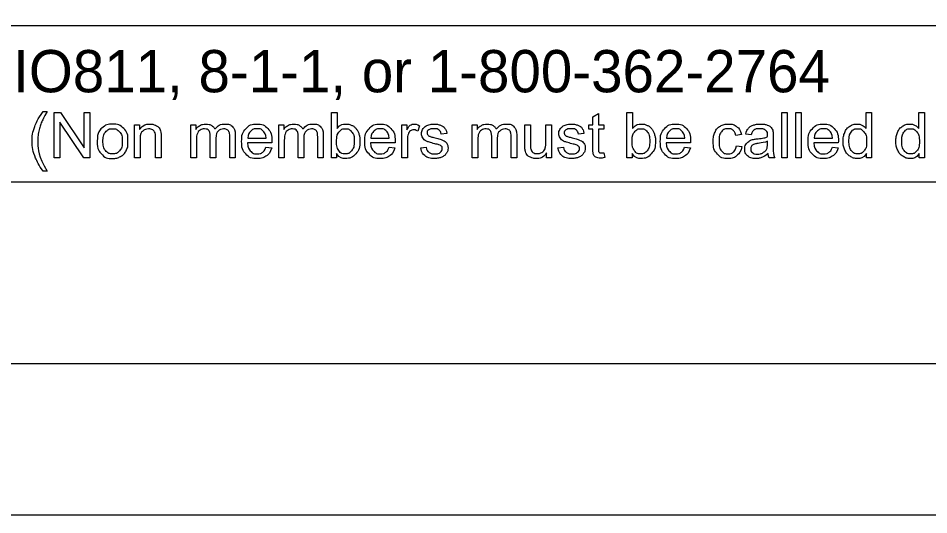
# Model space of a CAD drawing. Extents: x -20.5 to 34, y -66 to 23.9.
# Drawn here: x 15.219 to 18.236, y 0 to 1.645 of the extents above; entities that cross this region are included whole.
import ezdxf

# ---------------------------------------------------------------- set-up
doc = ezdxf.new("R2010")
doc.units = 0
for name, color, linetype in [('SH_Border', 7, 'Continuous'), ('SH_Cut_Line', 7, 'Continuous'), ('SH_Data', 7, 'Continuous'), ('SH_Text', 7, 'Continuous')]:
    doc.layers.add(name, color=color, linetype=linetype)

msp = doc.modelspace()

# ---------------------------------------------------------------- linework, layer by layer
at = {"layer": 'SH_Border'}
msp.add_lwpolyline([(1.5, 21.5), (33.5, 21.5), (33.5, 0.5), (1.5, 0.5)], close=True, dxfattribs=at)
at = {"layer": 'SH_Cut_Line'}
msp.add_lwpolyline([(0, 0), (34, 0), (34, 22), (0, 22)], close=True, dxfattribs=at)
at = {"layer": 'SH_Data'}
for p, q in [((19.1267, 1.6197), (14.8767, 1.6197)), ((19.1267, 1.1019), (14.8767, 1.1019))]:
    msp.add_line(p, q, dxfattribs=at)
at = {"layer": 'SH_Text'}
for points in [[(15.3013, 1.3357), (15.3145, 1.3357)], [(15.338, 1.183), (15.338, 1.3332), (15.3584, 1.3332), (15.4374, 1.2152), (15.4374, 1.3332), (15.4564, 1.3332), (15.4564, 1.183), (15.4361, 1.183), (15.357, 1.3009), (15.357, 1.183), (15.338, 1.183)], [(16.2735, 1.183), (16.2565, 1.183), (16.2565, 1.3332), (16.2749, 1.3332), (16.2749, 1.2797)], [(17.1225, 1.2149), (17.1225, 1.2775), (17.1088, 1.2775), (17.1088, 1.2919), (17.1225, 1.2919), (17.1225, 1.3188), (17.1409, 1.3299), (17.1409, 1.2919), (17.1593, 1.2919), (17.1593, 1.2775), (17.1409, 1.2775), (17.1409, 1.2138)], [(17.2526, 1.183), (17.2355, 1.183), (17.2355, 1.3332), (17.254, 1.3332), (17.254, 1.2797)], [(17.7482, 1.183), (17.7482, 1.3332), (17.7667, 1.3332), (17.7667, 1.183), (17.7482, 1.183)], [(17.7948, 1.183), (17.7948, 1.3332), (17.8132, 1.3332), (17.8132, 1.183), (17.7948, 1.183)], [(18.0277, 1.2793), (18.0277, 1.3332), (18.0461, 1.3332), (18.0461, 1.183), (18.0291, 1.183)], [(18.2026, 1.2793), (18.2026, 1.3332), (18.221, 1.3332), (18.221, 1.183), (18.2039, 1.183)], [(15.604, 1.183), (15.604, 1.2919), (15.6206, 1.2919), (15.6206, 1.2764)], [(15.7904, 1.183), (15.7904, 1.2919), (15.8069, 1.2919), (15.8069, 1.2765)], [(16.0818, 1.183), (16.0818, 1.2919), (16.0983, 1.2919), (16.0983, 1.2765)], [(16.4896, 1.183), (16.4896, 1.2919), (16.5062, 1.2919), (16.5062, 1.2754)], [(16.5486, 1.2884), (16.5422, 1.2713)], [(16.7228, 1.183), (16.7228, 1.2919), (16.7393, 1.2919), (16.7393, 1.2765)], [(16.8971, 1.2245), (16.8971, 1.2919), (16.9155, 1.2919), (16.9155, 1.2315)], [(16.9668, 1.2336), (16.9668, 1.2919), (16.9852, 1.2919), (16.9852, 1.183), (16.9688, 1.183)], [(15.6224, 1.2424), (15.6224, 1.183), (15.604, 1.183)], [(15.6924, 1.2499), (15.6924, 1.183), (15.6739, 1.183), (15.6739, 1.2492)], [(15.8089, 1.2394), (15.8089, 1.183), (15.7904, 1.183)], [(15.8735, 1.2462), (15.8735, 1.183), (15.8551, 1.183), (15.8551, 1.2537)], [(15.9379, 1.2577), (15.9379, 1.183), (15.9195, 1.183), (15.9195, 1.2515)], [(15.979, 1.2478), (16.0398, 1.2478)], [(16.1002, 1.2394), (16.1002, 1.183), (16.0818, 1.183)], [(16.1649, 1.2462), (16.1649, 1.183), (16.1465, 1.183), (16.1465, 1.2537)], [(16.2293, 1.2577), (16.2293, 1.183), (16.2109, 1.183), (16.2109, 1.2515)], [(16.387, 1.2478), (16.4478, 1.2478)], [(16.508, 1.24), (16.508, 1.183), (16.4896, 1.183)], [(16.6386, 1.2637), (16.6205, 1.2613)], [(16.7412, 1.2394), (16.7412, 1.183), (16.7228, 1.183)], [(16.8059, 1.2462), (16.8059, 1.183), (16.7875, 1.183), (16.7875, 1.2537)], [(16.8703, 1.2577), (16.8703, 1.183), (16.8519, 1.183), (16.8519, 1.2515)], [(17.0932, 1.2637), (17.0751, 1.2613)], [(17.3661, 1.2478), (17.4269, 1.2478)], [(17.6146, 1.2598), (17.5966, 1.2571)], [(17.6471, 1.2583), (17.629, 1.2607)], [(17.7014, 1.2309), (17.7015, 1.2376)], [(17.7201, 1.2532), (17.7201, 1.2286)], [(17.8557, 1.2478), (17.9165, 1.2478)], [(16.0592, 1.2327), (15.978, 1.2327)], [(16.0396, 1.2181), (16.0587, 1.2157)], [(16.4672, 1.2327), (16.386, 1.2327)], [(16.4476, 1.2181), (16.4666, 1.2157)], [(16.5522, 1.2155), (16.5704, 1.2184)], [(17.0068, 1.2155), (17.0249, 1.2184)], [(17.4462, 1.2327), (17.3651, 1.2327)], [(17.4267, 1.2181), (17.4457, 1.2157)], [(17.5982, 1.2228), (17.6163, 1.2204)], [(17.9358, 1.2327), (17.8547, 1.2327)], [(17.9163, 1.2181), (17.9353, 1.2157)], [(16.2735, 1.1966), (16.2735, 1.183)], [(16.9688, 1.183), (16.9688, 1.1991)], [(17.1593, 1.1994), (17.1619, 1.1832)], [(17.2526, 1.1966), (17.2526, 1.183)], [(17.7259, 1.183), (17.7067, 1.183)], [(18.0291, 1.183), (18.0291, 1.1967)], [(18.2039, 1.183), (18.2039, 1.1967)], [(15.3145, 1.1388), (15.3013, 1.1388)]]:
    msp.add_lwpolyline(points, dxfattribs=at)
for points, degree in [([(15.3013, 1.1388), (15.286, 1.1581), (15.2755, 1.1839), (15.2649, 1.2097), (15.2649, 1.2374), (15.2649, 1.2617), (15.2728, 1.2841), (15.282, 1.31), (15.3013, 1.3357)], 3), ([(15.3145, 1.3357), (15.3021, 1.3144), (15.2981, 1.3053), (15.2919, 1.2911), (15.2883, 1.2758), (15.2839, 1.2566), (15.2839, 1.2373), (15.2839, 1.188), (15.3145, 1.1388)], 3), ([(15.4805, 1.2374), (15.4805, 1.2676), (15.4973, 1.2822), (15.5113, 1.2943), (15.5315, 1.2943), (15.5539, 1.2943), (15.5682, 1.2796), (15.5824, 1.2649), (15.5824, 1.239), (15.5824, 1.218), (15.5761, 1.206), (15.5698, 1.1939), (15.5578, 1.1873), (15.5457, 1.1806), (15.5315, 1.1806), (15.5087, 1.1806), (15.4946, 1.1953), (15.4805, 1.2099), (15.4805, 1.2374)], 3), ([(15.4995, 1.2374), (15.4995, 1.2165), (15.5086, 1.2061), (15.5177, 1.1957), (15.5315, 1.1957), (15.5452, 1.1957), (15.5543, 1.2062), (15.5634, 1.2166), (15.5634, 1.238), (15.5634, 1.2582), (15.5542, 1.2686), (15.5451, 1.279), (15.5315, 1.279), (15.5177, 1.279), (15.5086, 1.2687), (15.4995, 1.2583), (15.4995, 1.2374)], 3), ([(15.6206, 1.2764), (15.6326, 1.2943), (15.6552, 1.2943), (15.665, 1.2943), (15.6733, 1.2907), (15.6815, 1.2872), (15.6856, 1.2815), (15.6897, 1.2757), (15.6913, 1.2678), (15.6924, 1.2627), (15.6924, 1.2499)], 3), ([(15.6739, 1.2492), (15.6739, 1.2604), (15.6718, 1.266), (15.6696, 1.2716), (15.6642, 1.2749), (15.6587, 1.2782), (15.6513, 1.2782), (15.6395, 1.2782), (15.631, 1.2708), (15.6224, 1.2633), (15.6224, 1.2424)], 3), ([(15.8069, 1.2765), (15.812, 1.2845), (15.8205, 1.2894), (15.829, 1.2943), (15.8399, 1.2943), (15.852, 1.2943), (15.8597, 1.2892), (15.8675, 1.2842), (15.8706, 1.2752), (15.8836, 1.2943), (15.9043, 1.2943), (15.9205, 1.2943), (15.9292, 1.2853), (15.9379, 1.2763), (15.9379, 1.2577)], 3), ([(15.8551, 1.2537), (15.8551, 1.2659), (15.8506, 1.2721), (15.8461, 1.2782), (15.8358, 1.2782), (15.828, 1.2782), (15.8214, 1.2741), (15.8148, 1.27), (15.8118, 1.2622), (15.8089, 1.2543), (15.8089, 1.2394)], 3), ([(15.9195, 1.2515), (15.9195, 1.2626), (15.9177, 1.2674), (15.9159, 1.2723), (15.9112, 1.2753), (15.9065, 1.2782), (15.9002, 1.2782), (15.8887, 1.2782), (15.8811, 1.2706), (15.8735, 1.263), (15.8735, 1.2462)], 3), ([(16.0587, 1.2157), (16.0542, 1.1991), (16.042, 1.1898), (16.0298, 1.1806), (16.0108, 1.1806), (15.987, 1.1806), (15.973, 1.1953), (15.959, 1.21), (15.959, 1.2365), (15.959, 1.264), (15.9732, 1.2791), (15.9873, 1.2943), (16.0098, 1.2943), (16.0316, 1.2943), (16.0454, 1.2794), (16.0593, 1.2645), (16.0593, 1.2376), (16.0593, 1.236), (16.0592, 1.2327)], 3), ([(16.0398, 1.2478), (16.0386, 1.2616), (16.0328, 1.2685), (16.024, 1.2791), (16.01, 1.2791), (15.9973, 1.2791), (15.9886, 1.2706), (15.98, 1.2621), (15.979, 1.2478)], 3), ([(16.0983, 1.2765), (16.1034, 1.2845), (16.1119, 1.2894), (16.1204, 1.2943), (16.1313, 1.2943), (16.1434, 1.2943), (16.1511, 1.2892), (16.1588, 1.2842), (16.162, 1.2752), (16.1749, 1.2943), (16.1957, 1.2943), (16.2119, 1.2943), (16.2206, 1.2853), (16.2293, 1.2763), (16.2293, 1.2577)], 3), ([(16.1465, 1.2537), (16.1465, 1.2659), (16.1419, 1.2721), (16.1374, 1.2782), (16.1272, 1.2782), (16.1194, 1.2782), (16.1128, 1.2741), (16.1062, 1.27), (16.1032, 1.2622), (16.1002, 1.2543), (16.1002, 1.2394)], 3), ([(16.2109, 1.2515), (16.2109, 1.2626), (16.2091, 1.2674), (16.2073, 1.2723), (16.2026, 1.2753), (16.1979, 1.2782), (16.1915, 1.2782), (16.18, 1.2782), (16.1725, 1.2706), (16.1649, 1.263), (16.1649, 1.2462)], 3), ([(16.2733, 1.2383), (16.2733, 1.2187), (16.2786, 1.21), (16.2873, 1.1957), (16.3021, 1.1957), (16.3142, 1.1957), (16.323, 1.2062), (16.3318, 1.2167), (16.3318, 1.2375), (16.3318, 1.2589), (16.3233, 1.269), (16.3149, 1.2791), (16.3029, 1.2791), (16.2909, 1.2791), (16.2821, 1.2686), (16.2733, 1.2581), (16.2733, 1.2383)], 3), ([(16.2749, 1.2797), (16.2866, 1.2943), (16.3047, 1.2943), (16.3147, 1.2943), (16.3237, 1.2902), (16.3326, 1.2862), (16.3384, 1.2788), (16.3442, 1.2715), (16.3475, 1.2612), (16.3508, 1.2508), (16.3508, 1.2391), (16.3508, 1.2111), (16.3369, 1.1959), (16.3231, 1.1806), (16.3037, 1.1806), (16.2845, 1.1806), (16.2735, 1.1966)], 3), ([(16.4666, 1.2157), (16.4621, 1.1991), (16.45, 1.1898), (16.4378, 1.1806), (16.4188, 1.1806), (16.395, 1.1806), (16.381, 1.1953), (16.367, 1.21), (16.367, 1.2365), (16.367, 1.264), (16.3811, 1.2791), (16.3953, 1.2943), (16.4178, 1.2943), (16.4396, 1.2943), (16.4534, 1.2794), (16.4673, 1.2645), (16.4673, 1.2376), (16.4673, 1.236), (16.4672, 1.2327)], 3), ([(16.4478, 1.2478), (16.4466, 1.2616), (16.4408, 1.2685), (16.432, 1.2791), (16.418, 1.2791), (16.4053, 1.2791), (16.3966, 1.2706), (16.388, 1.2621), (16.387, 1.2478)], 3), ([(16.5062, 1.2754), (16.5125, 1.2869), (16.5179, 1.2906), (16.5233, 1.2943), (16.5297, 1.2943), (16.539, 1.2943), (16.5486, 1.2884)], 3), ([(16.5422, 1.2713), (16.5354, 1.2753), (16.5287, 1.2753), (16.5227, 1.2753), (16.5179, 1.2716), (16.5131, 1.268), (16.5111, 1.2615), (16.508, 1.2517), (16.508, 1.24)], 3), ([(16.6205, 1.2613), (16.6193, 1.2697), (16.6134, 1.2744), (16.6075, 1.2791), (16.5967, 1.2791), (16.584, 1.2791), (16.5786, 1.2749), (16.5731, 1.2707), (16.5731, 1.2651), (16.5731, 1.2615), (16.5754, 1.2586), (16.5776, 1.2557), (16.5825, 1.2537), (16.5852, 1.2527), (16.5988, 1.249), (16.6184, 1.2438), (16.6261, 1.2404), (16.6339, 1.2371), (16.6383, 1.2308), (16.6427, 1.2244), (16.6427, 1.215), (16.6427, 1.2058), (16.6373, 1.1977), (16.6319, 1.1895), (16.6218, 1.1851), (16.6116, 1.1806), (16.5988, 1.1806), (16.5775, 1.1806), (16.5664, 1.1894), (16.5553, 1.1982), (16.5522, 1.2155)], 3), ([(16.5704, 1.2184), (16.5719, 1.2074), (16.579, 1.2016), (16.586, 1.1957), (16.5986, 1.1957), (16.6114, 1.1957), (16.6175, 1.2009), (16.6237, 1.2061), (16.6237, 1.2131), (16.6237, 1.2193), (16.6183, 1.2229), (16.6145, 1.2254), (16.5994, 1.2292), (16.5791, 1.2343), (16.5712, 1.238), (16.5634, 1.2418), (16.5593, 1.2484), (16.5553, 1.255), (16.5553, 1.2629), (16.5553, 1.2702), (16.5586, 1.2764), (16.5619, 1.2826), (16.5677, 1.2867), (16.572, 1.2899), (16.5794, 1.2921), (16.5869, 1.2943), (16.5954, 1.2943), (16.6082, 1.2943), (16.6179, 1.2906), (16.6276, 1.2869), (16.6322, 1.2806), (16.6368, 1.2743), (16.6386, 1.2637)], 3), ([(16.7393, 1.2765), (16.7444, 1.2845), (16.7529, 1.2894), (16.7614, 1.2943), (16.7723, 1.2943), (16.7844, 1.2943), (16.7921, 1.2892), (16.7998, 1.2842), (16.803, 1.2752), (16.8159, 1.2943), (16.8367, 1.2943), (16.8529, 1.2943), (16.8616, 1.2853), (16.8703, 1.2763), (16.8703, 1.2577)], 3), ([(16.7875, 1.2537), (16.7875, 1.2659), (16.7829, 1.2721), (16.7784, 1.2782), (16.7682, 1.2782), (16.7604, 1.2782), (16.7538, 1.2741), (16.7472, 1.27), (16.7442, 1.2622), (16.7412, 1.2543), (16.7412, 1.2394)], 3), ([(16.8519, 1.2515), (16.8519, 1.2626), (16.8501, 1.2674), (16.8483, 1.2723), (16.8436, 1.2753), (16.8389, 1.2782), (16.8325, 1.2782), (16.821, 1.2782), (16.8135, 1.2706), (16.8059, 1.263), (16.8059, 1.2462)], 3), ([(17.0751, 1.2613), (17.0738, 1.2697), (17.0679, 1.2744), (17.062, 1.2791), (17.0513, 1.2791), (17.0386, 1.2791), (17.0331, 1.2749), (17.0277, 1.2707), (17.0277, 1.2651), (17.0277, 1.2615), (17.03, 1.2586), (17.0322, 1.2557), (17.037, 1.2537), (17.0398, 1.2527), (17.0533, 1.249), (17.0729, 1.2438), (17.0807, 1.2404), (17.0884, 1.2371), (17.0929, 1.2308), (17.0973, 1.2244), (17.0973, 1.215), (17.0973, 1.2058), (17.0919, 1.1977), (17.0865, 1.1895), (17.0763, 1.1851), (17.0662, 1.1806), (17.0533, 1.1806), (17.0321, 1.1806), (17.021, 1.1894), (17.0098, 1.1982), (17.0068, 1.2155)], 3), ([(17.0249, 1.2184), (17.0265, 1.2074), (17.0335, 1.2016), (17.0406, 1.1957), (17.0532, 1.1957), (17.0659, 1.1957), (17.0721, 1.2009), (17.0783, 1.2061), (17.0783, 1.2131), (17.0783, 1.2193), (17.0728, 1.2229), (17.069, 1.2254), (17.0539, 1.2292), (17.0336, 1.2343), (17.0258, 1.238), (17.0179, 1.2418), (17.0139, 1.2484), (17.0098, 1.255), (17.0098, 1.2629), (17.0098, 1.2702), (17.0132, 1.2764), (17.0165, 1.2826), (17.0223, 1.2867), (17.0266, 1.2899), (17.034, 1.2921), (17.0414, 1.2943), (17.05, 1.2943), (17.0628, 1.2943), (17.0725, 1.2906), (17.0822, 1.2869), (17.0868, 1.2806), (17.0914, 1.2743), (17.0932, 1.2637)], 3), ([(17.2523, 1.2383), (17.2523, 1.2187), (17.2577, 1.21), (17.2664, 1.1957), (17.2812, 1.1957), (17.2932, 1.1957), (17.302, 1.2062), (17.3108, 1.2167), (17.3108, 1.2375), (17.3108, 1.2589), (17.3024, 1.269), (17.294, 1.2791), (17.282, 1.2791), (17.2699, 1.2791), (17.2611, 1.2686), (17.2523, 1.2581), (17.2523, 1.2383)], 3), ([(17.254, 1.2797), (17.2656, 1.2943), (17.2837, 1.2943), (17.2938, 1.2943), (17.3027, 1.2902), (17.3117, 1.2862), (17.3175, 1.2788), (17.3233, 1.2715), (17.3265, 1.2612), (17.3298, 1.2508), (17.3298, 1.2391), (17.3298, 1.2111), (17.316, 1.1959), (17.3022, 1.1806), (17.2828, 1.1806), (17.2635, 1.1806), (17.2526, 1.1966)], 3), ([(17.4457, 1.2157), (17.4412, 1.1991), (17.429, 1.1898), (17.4168, 1.1806), (17.3979, 1.1806), (17.374, 1.1806), (17.3601, 1.1953), (17.3461, 1.21), (17.3461, 1.2365), (17.3461, 1.264), (17.3602, 1.2791), (17.3743, 1.2943), (17.3969, 1.2943), (17.4187, 1.2943), (17.4325, 1.2794), (17.4463, 1.2645), (17.4463, 1.2376), (17.4463, 1.236), (17.4462, 1.2327)], 3), ([(17.4269, 1.2478), (17.4256, 1.2616), (17.4199, 1.2685), (17.4111, 1.2791), (17.3971, 1.2791), (17.3843, 1.2791), (17.3757, 1.2706), (17.367, 1.2621), (17.3661, 1.2478)], 3), ([(17.6163, 1.2204), (17.6133, 1.2018), (17.6011, 1.1912), (17.5888, 1.1806), (17.571, 1.1806), (17.5487, 1.1806), (17.5351, 1.1952), (17.5215, 1.2098), (17.5215, 1.237), (17.5215, 1.2546), (17.5274, 1.2678), (17.5332, 1.281), (17.5451, 1.2877), (17.5571, 1.2943), (17.5711, 1.2943), (17.5888, 1.2943), (17.6001, 1.2853), (17.6114, 1.2763), (17.6146, 1.2598)], 3), ([(17.5966, 1.2571), (17.594, 1.2681), (17.5875, 1.2736), (17.581, 1.2791), (17.5718, 1.2791), (17.5579, 1.2791), (17.5492, 1.2692), (17.5405, 1.2592), (17.5405, 1.2375), (17.5405, 1.2156), (17.5489, 1.2057), (17.5573, 1.1957), (17.5708, 1.1957), (17.5817, 1.1957), (17.589, 1.2024), (17.5962, 1.209), (17.5982, 1.2228)], 3), ([(17.703, 1.1964), (17.6927, 1.1877), (17.6833, 1.1842), (17.6738, 1.1806), (17.6629, 1.1806), (17.645, 1.1806), (17.6354, 1.1894), (17.6258, 1.1981), (17.6258, 1.2117), (17.6258, 1.2197), (17.6294, 1.2263), (17.633, 1.2329), (17.6389, 1.2369), (17.6448, 1.2409), (17.6522, 1.2429), (17.6576, 1.2444), (17.6686, 1.2457), (17.6909, 1.2483), (17.7014, 1.252), (17.7015, 1.2558), (17.7015, 1.2569), (17.7015, 1.2681), (17.6963, 1.2728), (17.6893, 1.279), (17.6754, 1.279), (17.6624, 1.279), (17.6562, 1.2745), (17.65, 1.2699), (17.6471, 1.2583)], 3), ([(17.629, 1.2607), (17.6314, 1.2723), (17.6371, 1.2794), (17.6427, 1.2866), (17.6533, 1.2904), (17.664, 1.2943), (17.678, 1.2943), (17.6919, 1.2943), (17.7006, 1.291), (17.7093, 1.2877), (17.7134, 1.2827), (17.7175, 1.2778), (17.7192, 1.2702), (17.7201, 1.2655), (17.7201, 1.2532)], 3), ([(17.9353, 1.2157), (17.9308, 1.1991), (17.9186, 1.1898), (17.9064, 1.1806), (17.8875, 1.1806), (17.8636, 1.1806), (17.8496, 1.1953), (17.8357, 1.21), (17.8357, 1.2365), (17.8357, 1.264), (17.8498, 1.2791), (17.8639, 1.2943), (17.8865, 1.2943), (17.9083, 1.2943), (17.9221, 1.2794), (17.9359, 1.2645), (17.9359, 1.2376), (17.9359, 1.236), (17.9358, 1.2327)], 3), ([(17.9165, 1.2478), (17.9152, 1.2616), (17.9095, 1.2685), (17.9007, 1.2791), (17.8866, 1.2791), (17.8739, 1.2791), (17.8653, 1.2706), (17.8566, 1.2621), (17.8557, 1.2478)], 3), ([(18.0291, 1.1967), (18.0187, 1.1806), (17.9986, 1.1806), (17.9856, 1.1806), (17.9747, 1.1878), (17.9638, 1.1949), (17.9578, 1.2078), (17.9518, 1.2206), (17.9518, 1.2373), (17.9518, 1.2536), (17.9572, 1.2669), (17.9627, 1.2801), (17.9735, 1.2872), (17.9843, 1.2943), (17.9977, 1.2943), (18.0076, 1.2943), (18.0152, 1.2901), (18.0229, 1.286), (18.0277, 1.2793)], 3), ([(17.9708, 1.2373), (17.9708, 1.2164), (17.9796, 1.2061), (17.9884, 1.1957), (18.0004, 1.1957), (18.0125, 1.1957), (18.021, 1.2056), (18.0294, 1.2155), (18.0294, 1.2358), (18.0294, 1.2581), (18.0208, 1.2686), (18.0122, 1.279), (17.9996, 1.279), (17.9873, 1.279), (17.9791, 1.269), (17.9708, 1.2589), (17.9708, 1.2373)], 3), ([(18.2039, 1.1967), (18.1936, 1.1806), (18.1735, 1.1806), (18.1605, 1.1806), (18.1496, 1.1878), (18.1387, 1.1949), (18.1327, 1.2078), (18.1267, 1.2206), (18.1267, 1.2373), (18.1267, 1.2536), (18.1321, 1.2669), (18.1375, 1.2801), (18.1484, 1.2872), (18.1592, 1.2943), (18.1726, 1.2943), (18.1824, 1.2943), (18.1901, 1.2901), (18.1978, 1.286), (18.2026, 1.2793)], 3), ([(18.1457, 1.2373), (18.1457, 1.2164), (18.1545, 1.2061), (18.1633, 1.1957), (18.1753, 1.1957), (18.1874, 1.1957), (18.1958, 1.2056), (18.2043, 1.2155), (18.2043, 1.2358), (18.2043, 1.2581), (18.1957, 1.2686), (18.1871, 1.279), (18.1745, 1.279), (18.1622, 1.279), (18.1539, 1.269), (18.1457, 1.2589), (18.1457, 1.2373)], 3), ([(17.7015, 1.2376), (17.6915, 1.2335), (17.6714, 1.2306), (17.66, 1.229), (17.6553, 1.227), (17.6506, 1.2249), (17.648, 1.221), (17.6455, 1.217), (17.6455, 1.2122), (17.6455, 1.2049), (17.651, 1.1999), (17.6566, 1.195), (17.6674, 1.195), (17.678, 1.195), (17.6863, 1.1997), (17.6946, 1.2044), (17.6985, 1.2124), (17.7014, 1.2187), (17.7014, 1.2309)], 3), ([(15.978, 1.2327), (15.979, 1.2148), (15.9882, 1.2052), (15.9973, 1.1957), (16.0109, 1.1957), (16.0211, 1.1957), (16.0282, 1.2011), (16.0354, 1.2064), (16.0396, 1.2181)], 3), ([(16.386, 1.2327), (16.387, 1.2148), (16.3962, 1.2052), (16.4053, 1.1957), (16.4189, 1.1957), (16.4291, 1.1957), (16.4362, 1.2011), (16.4434, 1.2064), (16.4476, 1.2181)], 3), ([(16.9688, 1.1991), (16.9561, 1.1806), (16.9343, 1.1806), (16.9246, 1.1806), (16.9163, 1.1843), (16.908, 1.188), (16.9039, 1.1936), (16.8999, 1.1992), (16.8982, 1.2072), (16.8971, 1.2127), (16.8971, 1.2245)], 3), ([(16.9155, 1.2315), (16.9155, 1.2171), (16.9167, 1.2121), (16.9184, 1.2048), (16.924, 1.2007), (16.9297, 1.1965), (16.938, 1.1965), (16.9462, 1.1965), (16.9535, 1.2008), (16.9608, 1.205), (16.9638, 1.2123), (16.9668, 1.2197), (16.9668, 1.2336)], 3), ([(17.1619, 1.1832), (17.1542, 1.1815), (17.148, 1.1815), (17.138, 1.1815), (17.1325, 1.1847), (17.127, 1.1879), (17.1247, 1.1931), (17.1225, 1.1982), (17.1225, 1.2149)], 3), ([(17.1409, 1.2138), (17.1409, 1.2059), (17.1418, 1.2036), (17.1428, 1.2014), (17.145, 1.2), (17.1472, 1.1987), (17.1513, 1.1987), (17.1543, 1.1987), (17.1593, 1.1994)], 3), ([(17.3651, 1.2327), (17.3661, 1.2148), (17.3752, 1.2052), (17.3843, 1.1957), (17.398, 1.1957), (17.4081, 1.1957), (17.4153, 1.2011), (17.4225, 1.2064), (17.4267, 1.2181)], 3), ([(17.7201, 1.2286), (17.7201, 1.2029), (17.7213, 1.1961), (17.7224, 1.1893), (17.7259, 1.183)], 3), ([(17.8547, 1.2327), (17.8557, 1.2148), (17.8648, 1.2052), (17.8739, 1.1957), (17.8876, 1.1957), (17.8977, 1.1957), (17.9049, 1.2011), (17.9121, 1.2064), (17.9163, 1.2181)], 3), ([(17.7067, 1.183), (17.7038, 1.1887), (17.703, 1.1964)], 2)]:
    msp.add_open_spline(points, degree=degree, dxfattribs=at)

# ---------------------------------------------------------------- texts
msp.add_text('OHIO811, 8-1-1, or 1-800-362-2764', height=0.14, dxfattribs=at).set_placement((14.9212, 1.3997))

doc.saveas('drawing.dxf')
